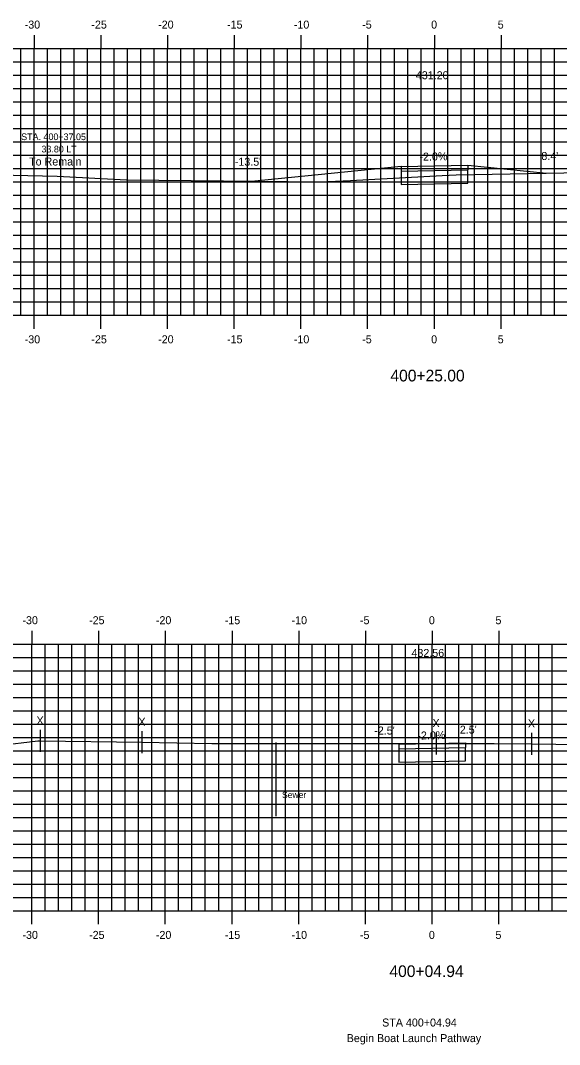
# Model space of a CAD drawing. Extents: x -161 to 764, y 111 to 210.
# Drawn here: x -118.7 to -78.3, y 123.7 to 200.5 of the extents above; entities that cross this region are included whole.
import ezdxf

# ---------------------------------------------------------------- set-up
doc = ezdxf.new("R2010")
doc.units = 0
for name, color, linetype in [('D_Property_Walkway_Paved', 7, 'Continuous'), ('D_Roadway_Centerline_Text', 7, 'Continuous'), ('D_Roadway_SubGrade', 7, 'Continuous'), ('D_Slope_Cut', 7, 'Continuous'), ('D_Text_Monospaced', 7, 'Continuous'), ('D_Text_Standard', 7, 'Continuous'), ('H_V ANNOTATION', 7, 'Continuous'), ('MAJOR', 7, 'Continuous'), ('MINOR', 7, 'Continuous'), ('S_Roadway_Centerline', 7, 'Continuous'), ('S_Roadway_Edge_Pavement', 7, 'Continuous'), ('S_Utilities_UG_Sanitary_Sewer', 7, 'Continuous')]:
    doc.layers.add(name, color=color, linetype=linetype)

msp = doc.modelspace()

# ---------------------------------------------------------------- linework, layer by layer
at = {"layer": 'D_Property_Walkway_Paved'}
for p, q in [((-90.186, 189.586), (-85.186, 189.686)), ((-85.186, 189.686), (-85.186, 189.342)), ((-90.186, 189.586), (-90.186, 189.242)), ((-90.186, 189.242), (-85.186, 189.342)), ((-90.363, 146.278), (-85.364, 146.378)), ((-90.363, 146.278), (-90.363, 145.935)), ((-90.363, 145.935), (-85.364, 146.035)), ((-85.364, 146.378), (-85.364, 146.035))]:
    msp.add_line(p, q, dxfattribs=at)
at = {"layer": 'D_Roadway_SubGrade'}
for p, q in [((-90.186, 189.242), (-90.186, 188.242)), ((-90.363, 145.935), (-90.363, 144.935))]:
    msp.add_line(p, q, dxfattribs=at)
for points in [[(-90.186, 188.242), (-85.186, 188.342), (-85.186, 189.342)], [(-90.363, 144.935), (-85.363, 145.035), (-85.364, 146.035)]]:
    msp.add_lwpolyline(points, dxfattribs=at)
at = {"layer": 'D_Slope_Cut'}
for p, q in [((-85.186, 189.686), (-79.288, 189.096)), ((-90.186, 189.586), (-101.147, 188.49))]:
    msp.add_line(p, q, dxfattribs=at)
at = {"layer": 'MAJOR'}
for p, q in [((-117.693, 199.435), (-117.693, 198.433)), ((-112.693, 199.435), (-112.693, 198.433)), ((-107.693, 199.435), (-107.693, 198.433)), ((-102.693, 199.435), (-102.693, 198.433)), ((-97.693, 199.435), (-97.693, 198.433)), ((-92.693, 199.435), (-92.693, 198.433)), ((-87.693, 199.435), (-87.693, 198.433)), ((-82.693, 199.435), (-82.693, 198.433)), ((-157.693, 198.433), (-17.693, 198.433)), ((-157.693, 198.433), (-17.693, 198.433)), ((-117.693, 178.433), (-117.693, 198.433)), ((-112.693, 178.433), (-112.693, 198.433)), ((-107.693, 178.433), (-107.693, 198.433)), ((-102.693, 178.433), (-102.693, 198.433)), ((-97.693, 178.433), (-97.693, 198.433)), ((-92.693, 178.433), (-92.693, 198.433)), ((-87.693, 178.433), (-87.693, 198.433)), ((-82.693, 178.433), (-82.693, 198.433)), ((-157.693, 193.433), (-17.693, 193.433)), ((-157.693, 188.433), (-17.693, 188.433)), ((-157.693, 183.433), (-17.693, 183.433)), ((-157.693, 178.433), (-17.693, 178.433)), ((-157.693, 178.433), (-17.693, 178.433)), ((-117.693, 177.431), (-117.693, 178.433)), ((-112.693, 177.431), (-112.693, 178.433)), ((-107.693, 177.431), (-107.693, 178.433)), ((-102.693, 177.431), (-102.693, 178.433)), ((-97.693, 177.431), (-97.693, 178.433)), ((-92.693, 177.431), (-92.693, 178.433)), ((-87.693, 177.431), (-87.693, 178.433)), ((-82.693, 177.431), (-82.693, 178.433)), ((-117.863, 154.77), (-117.863, 153.768)), ((-112.863, 154.77), (-112.863, 153.768)), ((-107.863, 154.77), (-107.863, 153.768)), ((-102.863, 154.77), (-102.863, 153.768)), ((-97.863, 154.77), (-97.863, 153.768)), ((-92.863, 154.77), (-92.863, 153.768)), ((-87.863, 154.77), (-87.863, 153.768)), ((-82.863, 154.77), (-82.863, 153.768)), ((-157.863, 153.768), (-17.863, 153.768)), ((-157.863, 153.768), (-17.863, 153.768)), ((-117.863, 133.768), (-117.863, 153.768)), ((-112.863, 133.768), (-112.863, 153.768)), ((-107.863, 133.768), (-107.863, 153.768)), ((-102.863, 133.768), (-102.863, 153.768)), ((-97.863, 133.768), (-97.863, 153.768)), ((-92.863, 133.768), (-92.863, 153.768)), ((-87.863, 133.768), (-87.863, 153.768)), ((-82.863, 133.768), (-82.863, 153.768)), ((-157.863, 148.768), (-17.863, 148.768)), ((-157.863, 143.768), (-17.863, 143.768)), ((-157.863, 138.768), (-17.863, 138.768)), ((-157.863, 133.768), (-17.863, 133.768)), ((-157.863, 133.768), (-17.863, 133.768)), ((-117.863, 132.766), (-117.863, 133.768)), ((-112.863, 132.766), (-112.863, 133.768)), ((-107.863, 132.766), (-107.863, 133.768)), ((-102.863, 132.766), (-102.863, 133.768)), ((-97.863, 132.766), (-97.863, 133.768)), ((-92.863, 132.766), (-92.863, 133.768)), ((-87.863, 132.766), (-87.863, 133.768)), ((-82.863, 132.766), (-82.863, 133.768))]:
    msp.add_line(p, q, dxfattribs=at)
at = {"layer": 'MINOR'}
for p, q in [((-118.693, 178.433), (-118.693, 198.433)), ((-116.693, 178.433), (-116.693, 198.433)), ((-115.693, 178.433), (-115.693, 198.433)), ((-114.693, 178.433), (-114.693, 198.433)), ((-113.693, 178.433), (-113.693, 198.433)), ((-111.693, 178.433), (-111.693, 198.433)), ((-110.693, 178.433), (-110.693, 198.433)), ((-109.693, 178.433), (-109.693, 198.433)), ((-108.693, 178.433), (-108.693, 198.433)), ((-106.693, 178.433), (-106.693, 198.433)), ((-105.693, 178.433), (-105.693, 198.433)), ((-104.693, 178.433), (-104.693, 198.433)), ((-103.693, 178.433), (-103.693, 198.433)), ((-101.693, 178.433), (-101.693, 198.433)), ((-100.693, 178.433), (-100.693, 198.433)), ((-99.693, 178.433), (-99.693, 198.433)), ((-98.693, 178.433), (-98.693, 198.433)), ((-96.693, 178.433), (-96.693, 198.433)), ((-95.693, 178.433), (-95.693, 198.433)), ((-94.693, 178.433), (-94.693, 198.433)), ((-93.693, 178.433), (-93.693, 198.433)), ((-91.693, 178.433), (-91.693, 198.433)), ((-90.693, 178.433), (-90.693, 198.433)), ((-89.693, 178.433), (-89.693, 198.433)), ((-88.693, 178.433), (-88.693, 198.433)), ((-86.693, 178.433), (-86.693, 198.433)), ((-85.693, 178.433), (-85.693, 198.433)), ((-84.693, 178.433), (-84.693, 198.433)), ((-83.693, 178.433), (-83.693, 198.433)), ((-81.693, 178.433), (-81.693, 198.433)), ((-80.693, 178.433), (-80.693, 198.433)), ((-79.693, 178.433), (-79.693, 198.433)), ((-78.693, 178.433), (-78.693, 198.433)), ((-157.693, 197.433), (-17.693, 197.433)), ((-157.693, 196.433), (-17.693, 196.433)), ((-157.693, 195.433), (-17.693, 195.433)), ((-157.693, 194.433), (-17.693, 194.433)), ((-157.693, 192.433), (-17.693, 192.433)), ((-157.693, 191.433), (-17.693, 191.433)), ((-157.693, 190.433), (-17.693, 190.433)), ((-157.693, 189.433), (-17.693, 189.433)), ((-157.693, 187.433), (-17.693, 187.433)), ((-157.693, 186.433), (-17.693, 186.433)), ((-157.693, 185.433), (-17.693, 185.433)), ((-157.693, 184.433), (-17.693, 184.433)), ((-157.693, 182.433), (-17.693, 182.433)), ((-157.693, 181.433), (-17.693, 181.433)), ((-157.693, 180.433), (-17.693, 180.433)), ((-157.693, 179.433), (-17.693, 179.433)), ((-116.863, 133.768), (-116.863, 153.768)), ((-115.863, 133.768), (-115.863, 153.768)), ((-114.863, 133.768), (-114.863, 153.768)), ((-113.863, 133.768), (-113.863, 153.768)), ((-111.863, 133.768), (-111.863, 153.768)), ((-110.863, 133.768), (-110.863, 153.768)), ((-109.863, 133.768), (-109.863, 153.768)), ((-108.863, 133.768), (-108.863, 153.768)), ((-106.863, 133.768), (-106.863, 153.768)), ((-105.863, 133.768), (-105.863, 153.768)), ((-104.863, 133.768), (-104.863, 153.768)), ((-103.863, 133.768), (-103.863, 153.768)), ((-101.863, 133.768), (-101.863, 153.768)), ((-100.863, 133.768), (-100.863, 153.768)), ((-99.863, 133.768), (-99.863, 153.768)), ((-98.863, 133.768), (-98.863, 153.768)), ((-96.863, 133.768), (-96.863, 153.768)), ((-95.863, 133.768), (-95.863, 153.768)), ((-94.863, 133.768), (-94.863, 153.768)), ((-93.863, 133.768), (-93.863, 153.768)), ((-91.863, 133.768), (-91.863, 153.768)), ((-90.863, 133.768), (-90.863, 153.768)), ((-89.863, 133.768), (-89.863, 153.768)), ((-88.863, 133.768), (-88.863, 153.768)), ((-86.863, 133.768), (-86.863, 153.768)), ((-85.863, 133.768), (-85.863, 153.768)), ((-84.863, 133.768), (-84.863, 153.768)), ((-83.863, 133.768), (-83.863, 153.768)), ((-81.863, 133.768), (-81.863, 153.768)), ((-80.863, 133.768), (-80.863, 153.768)), ((-79.863, 133.768), (-79.863, 153.768)), ((-78.863, 133.768), (-78.863, 153.768)), ((-157.863, 152.768), (-17.863, 152.768)), ((-157.863, 151.768), (-17.863, 151.768)), ((-157.863, 150.768), (-17.863, 150.768)), ((-157.863, 149.768), (-17.863, 149.768)), ((-157.863, 147.768), (-17.863, 147.768)), ((-157.863, 146.768), (-17.863, 146.768)), ((-157.863, 145.768), (-17.863, 145.768)), ((-157.863, 144.768), (-17.863, 144.768)), ((-157.863, 142.768), (-17.863, 142.768)), ((-157.863, 141.768), (-17.863, 141.768)), ((-157.863, 140.768), (-17.863, 140.768)), ((-157.863, 139.768), (-17.863, 139.768)), ((-157.863, 137.768), (-17.863, 137.768)), ((-157.863, 136.768), (-17.863, 136.768)), ((-157.863, 135.768), (-17.863, 135.768)), ((-157.863, 134.768), (-17.863, 134.768))]:
    msp.add_line(p, q, dxfattribs=at)
at = {"layer": 'S_Roadway_Centerline'}
for points in [[(-157.693, 186.896), (-152.22, 186.735), (-150.498, 186.807), (-148.901, 186.975), (-141.893, 187.734), (-139.882, 188.09), (-132.124, 189.256), (-128.171, 189.315), (-121.467, 188.992), (-115.974, 188.872), (-110.769, 188.6), (-96.239, 188.433), (-93.99, 188.538), (-87.1, 188.918), (-86.065, 188.968), (-75.289, 189.172), (-68.973, 189.373), (-42.532, 188.98), (-34.493, 188.828), (-32.191, 188.81), (-29.47, 188.805), (-17.693, 188.431)], [(-157.863, 143.341), (-157.723, 143.12), (-157.491, 142.781), (-154.413, 143.007), (-152.205, 143.302), (-147.459, 144.078), (-146.374, 144.11), (-144.561, 144.195), (-133.827, 144.541), (-132.039, 144.763), (-130.463, 145.049), (-126.715, 145.433), (-120.377, 146.165), (-117.425, 146.515), (-117.256, 146.518), (-109.618, 146.417), (-104.371, 146.317), (-104.168, 146.321), (-87.565, 146.329), (-83.22, 146.326), (-80.412, 146.295), (-73.107, 146.205)]]:
    msp.add_lwpolyline(points, dxfattribs=at)
at = {"layer": 'S_Roadway_Edge_Pavement'}
for p, q in [((-117.256, 147.342), (-117.256, 145.694)), ((-109.618, 147.241), (-109.618, 145.593)), ((-87.565, 147.153), (-87.565, 145.505)), ((-80.412, 147.119), (-80.412, 145.471))]:
    msp.add_line(p, q, dxfattribs=at)
at = {"layer": 'S_Utilities_UG_Sanitary_Sewer'}
msp.add_line((-99.566, 146.401), (-99.566, 140.865), dxfattribs=at)

# ---------------------------------------------------------------- texts
at = {"layer": 'D_Roadway_Centerline_Text'}
for s, p in [('431.20', (-89.082, 196.136)), ('432.56', (-89.41, 152.813)), ('STA 400+04.94', (-91.608, 125.098)), ('Begin Boat Launch Pathway', (-94.264, 123.93))]:
    msp.add_text(s, height=0.6, dxfattribs=at).set_placement(p)
at = {"layer": 'D_Text_Monospaced'}
for s, height, p in [('STA. 400+37.05', 0.49998, (-118.667, 191.571)), ('33.80 LT', 0.5, (-117.147, 190.647))]:
    msp.add_text(s, height=height, dxfattribs=at).set_placement(p)
at = {"layer": 'D_Text_Standard'}
for p in [(-88.806, 190.021), (-88.962, 146.614)]:
    msp.add_text('-2.0%', height=0.6, rotation=1.14576, dxfattribs=at).set_placement(p)
for s, p in [("8.4'", (-79.671, 190.083)), ('To Remain', (-118.074, 189.666)), ("-13.5'", (-102.654, 189.65)), ("-2.5'", (-92.199, 146.994)), ("2.5'", (-85.784, 147.062))]:
    msp.add_text(s, height=0.6, dxfattribs=at).set_placement(p)
at = {"layer": 'H_V ANNOTATION'}
for s, height, p in [('-30', 0.6, (-118.405, 199.933)), ('-25', 0.6, (-113.408, 199.933)), ('-20', 0.6, (-108.4, 199.933)), ('-15', 0.6, (-103.236, 199.933)), ('-10', 0.6, (-98.228, 199.933)), ('-5', 0.6, (-93.103, 199.933)), ('0', 0.6, (-87.934, 199.933)), ('5', 0.6, (-82.942, 199.933)), ('-30', 0.6, (-118.405, 176.333)), ('-25', 0.6, (-113.408, 176.333)), ('-20', 0.6, (-108.4, 176.333)), ('-15', 0.6, (-103.236, 176.333)), ('-10', 0.6, (-98.228, 176.333)), ('-5', 0.6, (-93.103, 176.333)), ('0', 0.6, (-87.934, 176.333)), ('5', 0.6, (-82.942, 176.333)), ('400+25.00', 0.875, (-90.986, 173.476))]:
    msp.add_text(s, height=height, rotation=360, dxfattribs=at).set_placement(p)
for s, height, p in [('-30', 0.6, (-118.575, 155.268)), ('-25', 0.6, (-113.578, 155.268)), ('-20', 0.6, (-108.57, 155.268)), ('-15', 0.6, (-103.406, 155.268)), ('-10', 0.6, (-98.398, 155.268)), ('-5', 0.6, (-93.273, 155.268)), ('0', 0.6, (-88.104, 155.268)), ('5', 0.6, (-83.112, 155.268)), ('-30', 0.6, (-118.575, 131.668)), ('-25', 0.6, (-113.578, 131.668)), ('-20', 0.6, (-108.57, 131.668)), ('-15', 0.6, (-103.406, 131.668)), ('-10', 0.6, (-98.398, 131.668)), ('-5', 0.6, (-93.273, 131.668)), ('0', 0.6, (-88.104, 131.668)), ('5', 0.6, (-83.112, 131.668)), ('400+04.94', 0.875, (-91.062, 128.811))]:
    msp.add_text(s, height=height, dxfattribs=at).set_placement(p)
at = {"layer": 'S_Roadway_Edge_Pavement'}
for p in [(-117.521, 147.749), (-109.883, 147.648), (-87.83, 147.56), (-80.677, 147.526)]:
    msp.add_text('X', height=0.6, dxfattribs=at).set_placement(p)
at = {"layer": 'S_Utilities_UG_Sanitary_Sewer'}
msp.add_text('Sewer', height=0.4798, dxfattribs=at).set_placement((-99.115, 142.231))

doc.saveas('drawing.dxf')
